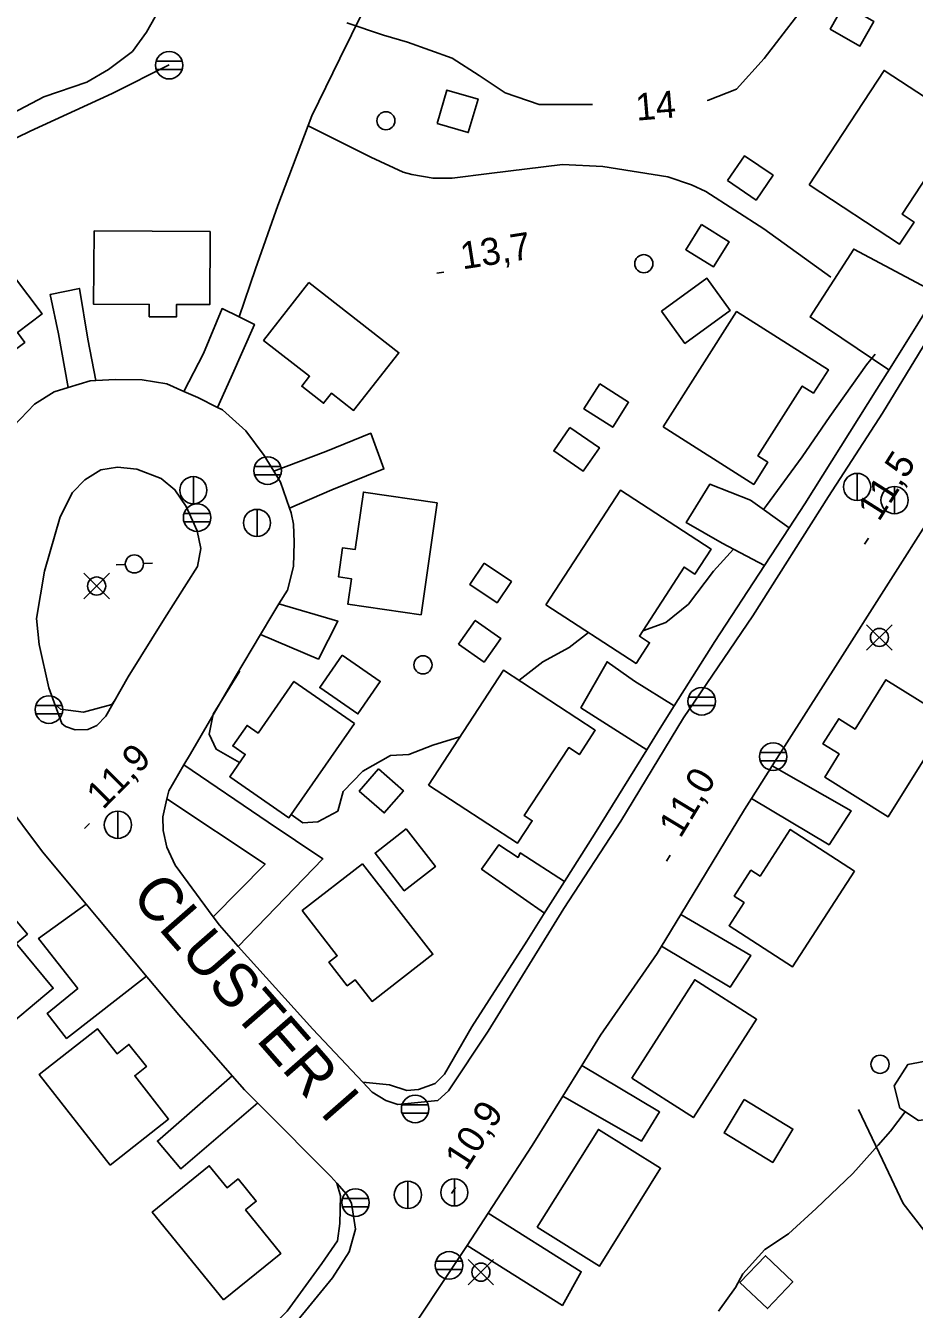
# Model space of a CAD drawing. Extents: x 646142 to 649934, y 5874075 to 5876351.
# Drawn here: x 647286.1 to 647384.4, y 5874712.1 to 5874854.1 of the extents above; entities that cross this region are included whole.
import ezdxf

# ---------------------------------------------------------------- set-up
doc = ezdxf.new("R2010")
doc.units = 0
for name, color, linetype in [('Niveau 1', 7, 'Continuous'), ('Niveau 15', 7, 'Continuous'), ('Niveau 19', 7, 'Continuous'), ('Niveau 2', 7, 'Continuous'), ('Niveau 21', 7, 'Continuous'), ('Niveau 22', 7, 'Continuous'), ('Niveau 3', 7, 'Continuous'), ('Niveau 31', 7, 'Continuous'), ('Niveau 36', 7, 'Continuous'), ('Niveau 4', 7, 'Continuous')]:
    doc.layers.add(name, color=color, linetype=linetype)

msp = doc.modelspace()

# ---------------------------------------------------------------- linework, layer by layer
at = {"layer": 'Niveau 1'}
msp.add_lwpolyline([(647362.71, 5874711.92), (647364.56, 5874714.57), (647365.4, 5874716.06), (647367.83, 5874718.75), (647370.42, 5874720.47), (647373.48, 5874723.29), (647377.56, 5874727.15), (647380.35, 5874730.3), (647381.72, 5874731.84), (647383.33, 5874734)], dxfattribs=at)
at = {"layer": 'Niveau 19'}
for points in [[(647386.86, 5874824.51), (647377.65, 5874829.4), (647372.83, 5874821.91), (647381.55, 5874816.04)], [(647290.78, 5874814.09), (647289.72, 5874820.05), (647288.81, 5874824.39), (647292.02, 5874825.05), (647292.94, 5874819.44), (647293.86, 5874814.87)], [(647303.58, 5874813.67), (647305.74, 5874817.85), (647307.81, 5874822.83), (647309.69, 5874821.91), (647311.38, 5874821.08), (647308.81, 5874815.24), (647307.29, 5874811.9)], [(647313.54, 5874804.83), (647319.29, 5874807.03), (647324.24, 5874809.04), (647325.69, 5874805.1), (647319.95, 5874802.78), (647315.26, 5874800.76)], [(647367.8, 5874794.42), (647363.1, 5874796.87), (647359.11, 5874799.17), (647361.73, 5874803.39), (647366.25, 5874801.62), (647370.51, 5874798.57)], [(647314.09, 5874790.16), (647320.61, 5874788.24), (647318.45, 5874784.06), (647312.06, 5874786.79)], [(647354.76, 5874774.03), (647347.49, 5874778.68), (647350.37, 5874783.76), (647353.4, 5874781.6), (647357.81, 5874778.89)], [(647303.59, 5874772.36), (647312.91, 5874766.03), (647318.95, 5874761.96), (647309.6, 5874752.27)], [(647368.64, 5874772.26), (647377.36, 5874767.28), (647374.93, 5874763.53), (647366.33, 5874768.63)], [(647306.81, 5874755.55), (647312.56, 5874761.38), (647301.7, 5874768.61)], [(647345.66, 5874759.45), (647340.78, 5874762.62), (647340.54, 5874762.13), (647338.42, 5874763.52), (647336.5, 5874760.84), (647343.46, 5874755.97)], [(647292.76, 5874756.96), (647287.52, 5874753.17), (647291.84, 5874747.64), (647288.47, 5874744.86), (647290.61, 5874742.11), (647299.43, 5874748.98)], [(647358.52, 5874755.81), (647366.26, 5874751.28), (647364, 5874747.78), (647356.4, 5874752.32)], [(647347.57, 5874739.09), (647356.19, 5874733.98), (647354.17, 5874730.74), (647345.49, 5874735.73)], [(647308.93, 5874737.97), (647300.65, 5874730.75), (647303.26, 5874727.66), (647311.74, 5874734.97)], [(647337.23, 5874722.77), (647347.52, 5874716.3), (647345.43, 5874712.58), (647334.9, 5874719.19)]]:
    msp.add_lwpolyline(points, dxfattribs=at)
at = {"layer": 'Niveau 2'}
for points in [[(647354.49, 5874871.09), (647359.08, 5874873.06), (647362.73, 5874876.86), (647365.08, 5874877.85), (647367.9, 5874878.83), (647371.65, 5874879.37), (647373.74, 5874878.88), (647375.58, 5874877.44), (647376.35, 5874875.13), (647376.55, 5874873.17), (647377.56, 5874868.38), (647377.64, 5874865.89), (647377.51, 5874863.72), (647376.44, 5874861), (647373.32, 5874857.73), (647367.74, 5874850.48), (647364.7, 5874847.1), (647361.6, 5874845.86), (647361.46, 5874845.85)], [(647301.22, 5874856.54), (647299.43, 5874853.4), (647297.89, 5874851.27), (647295.23, 5874849.26), (647292.86, 5874847.86), (647288.11, 5874846.23), (647283.22, 5874843.71), (647281.4, 5874842.6), (647274.57, 5874838.95), (647270.5, 5874836.4), (647267.73, 5874834.96), (647263.27, 5874833.3), (647258.98, 5874830.66), (647254.31, 5874826.48), (647252.48, 5874824.26), (647250.06, 5874819.3), (647248.47, 5874814.14), (647246.85, 5874811.65), (647246.13, 5874809.43)], [(647348.78, 5874845.41), (647342.87, 5874845.41), (647339.12, 5874846.67), (647336.24, 5874848.59), (647333.23, 5874850.51), (647328.32, 5874852.29), (647325.66, 5874853.08), (647321.61, 5874854.42)], [(647367.67, 5874800.6), (647367.99, 5874801.03), (647371.96, 5874806.44), (647375.02, 5874810.89), (647379.07, 5874816.59), (647380.02, 5874817.8)], [(647354.33, 5874787.19), (647356.88, 5874788.09), (647359.37, 5874790.14), (647362.16, 5874793.8), (647364.34, 5874796.22)], [(647340.63, 5874781.7), (647343.29, 5874783.77), (647346.18, 5874785.34), (647348.31, 5874787.01)], [(647309.68, 5874782.75), (647309.74, 5874782.69), (647306.82, 5874777.97), (647306.39, 5874775.77), (647307.15, 5874774.09), (647309.74, 5874772.61)], [(647289.28, 5874779.1), (647289.94, 5874778.52), (647292.49, 5874778.19), (647295.63, 5874779.03), (647295.87, 5874779.39)], [(647315.43, 5874766.86), (647316.75, 5874765.94), (647318.38, 5874766.04), (647320.6, 5874767.25), (647321.21, 5874769.41), (647323.38, 5874771.67), (647326.43, 5874773.38), (647328.47, 5874773.52), (647331.12, 5874774.54), (647334.1, 5874775.45)]]:
    msp.add_lwpolyline(points, dxfattribs=at)
at = {"layer": 'Niveau 21'}
for points in [[(647388.78, 5874824.3), (647380.85, 5874811.27), (647374.87, 5874802.04), (647366.48, 5874788.83), (647358.82, 5874777.56), (647351.88, 5874766.12), (647345.58, 5874756.49), (647337.21, 5874742.92), (647332.84, 5874736.29), (647331.65, 5874735.24), (647329.44, 5874735.02), (647327.23, 5874734.8), (647325.9, 5874735.25), (647324.4, 5874736.16), (647323.35, 5874737.27), (647317.82, 5874743.11), (647309.6, 5874752.27), (647307.51, 5874754.61), (647306.81, 5874755.55), (647302.61, 5874761.25), (647301.71, 5874763.27), (647301.29, 5874765.1), (647301.25, 5874766.61), (647301.7, 5874768.61), (647301.9, 5874769.48), (647303.59, 5874772.36), (647304.3, 5874773.57), (647309.3, 5874782.12), (647312.06, 5874786.79), (647313.41, 5874789.06), (647314.09, 5874790.16), (647315.02, 5874791.67), (647315.69, 5874794.31), (647315.77, 5874797), (647315.69, 5874798.97), (647315.44, 5874800.23), (647315.26, 5874800.76), (647314.28, 5874803.62), (647313.54, 5874804.83), (647312.46, 5874806.59), (647310.43, 5874809.3), (647307.85, 5874811.61), (647307.29, 5874811.9), (647305.13, 5874812.98), (647303.58, 5874813.67), (647301.7, 5874814.51), (647298.96, 5874814.93), (647296.03, 5874814.99), (647293.86, 5874814.87), (647293.23, 5874814.84)], [(647293.23, 5874814.84), (647290.78, 5874814.09), (647289.25, 5874813.63), (647287.05, 5874812.24), (647283.98, 5874809.02)], [(647301.45, 5874788.55), (647305.09, 5874794.28), (647305.47, 5874796.3), (647305.04, 5874798.24), (647303.84, 5874800.92), (647302.59, 5874802.78), (647301.06, 5874804.03), (647298.38, 5874805.05), (647296.25, 5874805.3), (647294.4, 5874805), (647292.64, 5874803.9), (647291.26, 5874802.48), (647289.89, 5874799.78), (647288.15, 5874793.77), (647287.27, 5874788.55), (647287.56, 5874785.66), (647288.63, 5874780.87), (647290.08, 5874776.92), (647290.47, 5874776.61), (647291.56, 5874776.25), (647292.96, 5874776.27), (647293.97, 5874776.72), (647294.93, 5874777.75), (647297.42, 5874782.08), (647301.45, 5874788.55)], [(647358.52, 5874755.81), (647365.56, 5874767.43), (647366.33, 5874768.63), (647368.64, 5874772.26), (647375.88, 5874783.64), (647386.6, 5874800.46)], [(647283.47, 5874768.71), (647287.94, 5874762.73), (647292.76, 5874756.96), (647294.07, 5874755.39), (647299.71, 5874748.65), (647303.01, 5874744.7), (647308.93, 5874737.97), (647310.3, 5874736.41), (647312.08, 5874734.62), (647319.84, 5874726.83), (647320.5, 5874726.09), (647321.56, 5874724.89), (647322.13, 5874723.89), (647322.54, 5874721.01), (647321.85, 5874718.48), (647320.03, 5874715.61), (647313.54, 5874707.71)], [(647327.95, 5874708.73), (647333.96, 5874717.75), (647334.9, 5874719.19), (647337.23, 5874722.77), (647342.09, 5874730.26), (647345.49, 5874735.73), (647347.57, 5874739.09), (647349.66, 5874742.47), (647355.91, 5874751.51), (647356.36, 5874752.25), (647358.52, 5874755.81)]]:
    msp.add_lwpolyline(points, dxfattribs=at)
at = {"layer": 'Niveau 22'}
for points in [[(647309.69, 5874821.91), (647311.5, 5874827.21), (647313.95, 5874834.21), (647317.74, 5874844.13), (647320.84, 5874850.49), (647325.98, 5874861.01), (647328.35, 5874865.31), (647330.56, 5874867.74), (647334.34, 5874871.3)], [(647317.33, 5874843.05), (647324.24, 5874839.59), (647327.82, 5874837.91), (647328.77, 5874837.67), (647331.14, 5874837.24), (647333.23, 5874837.26), (647337.35, 5874837.78), (647345.46, 5874838.75), (647349.9, 5874838.53), (647357.11, 5874837.38), (647359.72, 5874836.53), (647361.31, 5874835.77), (647367.71, 5874831.66), (647375.12, 5874826.3)], [(647323.35, 5874737.27), (647326.31, 5874736.97), (647328.25, 5874736.35), (647329.53, 5874736.47), (647331.35, 5874737.12), (647332.41, 5874738.16), (647335.41, 5874743.37), (647341.49, 5874752.86), (647343.35, 5874755.8), (647345.66, 5874759.45), (647348.98, 5874764.7), (647354.76, 5874774.03), (647356.24, 5874776.41), (647357.81, 5874778.89), (647362.3, 5874786), (647367.8, 5874794.42), (647370.51, 5874798.57), (647372.25, 5874801.23), (647380.22, 5874813.93), (647382.05, 5874816.84), (647387.44, 5874825.44)], [(647378.17, 5874734.25), (647380.85, 5874728.66), (647383.11, 5874723.85), (647385.41, 5874720.91)], [(647250.97, 5874680.43), (647253.53, 5874678.34), (647255.63, 5874677.25), (647256.83, 5874677.02), (647258.69, 5874677.2), (647261.06, 5874678.26), (647265.84, 5874680.96), (647272.1, 5874684.15), (647278.81, 5874687.78), (647280.57, 5874688.74), (647281.86, 5874689.4), (647289.51, 5874693.37), (647297.19, 5874697.64), (647301.94, 5874700.57), (647306.42, 5874703.94), (647309.99, 5874706.98), (647315.01, 5874711.93), (647318.82, 5874717.22), (647320.57, 5874719.73), (647320.84, 5874721.63), (647320.89, 5874724.68), (647320.5, 5874726.09)]]:
    msp.add_lwpolyline(points, dxfattribs=at)
at = {"layer": 'Niveau 3'}
for p, q in [((647331.55, 5874826.74), (647332.34, 5874826.87)), ((647378.86, 5874796.76), (647379.29, 5874797.44)), ((647292.59, 5874765.31), (647293.15, 5874765.88)), ((647356.96, 5874761.69), (647357.37, 5874762.38)), ((647333.17, 5874724.96), (647333.6, 5874725.63))]:
    msp.add_line(p, q, dxfattribs=at)
at = {"layer": 'Niveau 31'}
for points in [[(647376.6, 5874856.45), (647379.89, 5874854.57), (647378.34, 5874851.86), (647375.05, 5874853.74), (647376.6, 5874856.45)], [(647372.73, 5874836.5), (647381.01, 5874849.16), (647391.01, 5874842.62), (647389.3, 5874840.01), (647387.99, 5874840.86), (647383.02, 5874833.25), (647384.32, 5874832.4), (647382.73, 5874829.96), (647372.73, 5874836.5)], [(647331.58, 5874843.29), (647332.67, 5874847), (647336.11, 5874845.99), (647335.03, 5874842.29), (647331.58, 5874843.29)], [(647363.69, 5874836.99), (647365.58, 5874839.73), (647368.73, 5874837.57), (647366.85, 5874834.83), (647363.69, 5874836.99)], [(647293.64, 5874831.42), (647306.48, 5874831.35), (647306.44, 5874823.26), (647302.77, 5874823.28), (647302.76, 5874821.9), (647299.75, 5874821.92), (647299.75, 5874823.28), (647293.6, 5874823.31), (647293.64, 5874831.42)], [(647360.8, 5874832.11), (647363.86, 5874830.21), (647362.13, 5874827.44), (647359.07, 5874829.34), (647360.8, 5874832.11)], [(647272.93, 5874821.07), (647283.02, 5874828.69), (647287.89, 5874822.24), (647285.17, 5874820.18), (647285.99, 5874819.09), (647283.66, 5874817.33), (647282.8, 5874818.47), (647277.77, 5874814.67), (647272.93, 5874821.07)], [(647317.4, 5874825.72), (647327.35, 5874817.94), (647322.35, 5874811.56), (647319.91, 5874813.47), (647319.03, 5874812.35), (647316.61, 5874814.24), (647317.47, 5874815.34), (647312.39, 5874819.31), (647317.4, 5874825.72)], [(647356.4, 5874822.55), (647361.41, 5874826.18), (647364, 5874822.62), (647358.99, 5874818.98), (647356.4, 5874822.55)], [(647356.58, 5874809.73), (647364.69, 5874822.5), (647374.85, 5874816.06), (647373.2, 5874813.47), (647371.96, 5874814.26), (647367.05, 5874806.53), (647368.15, 5874805.83), (647366.59, 5874803.38), (647356.58, 5874809.73)], [(647349.56, 5874814.49), (647352.75, 5874812.47), (647351, 5874809.7), (647347.81, 5874811.72), (647349.56, 5874814.49)], [(647346.25, 5874809.68), (647349.52, 5874807.44), (647347.73, 5874804.84), (647344.47, 5874807.08), (647346.25, 5874809.68)], [(647343.62, 5874790.06), (647351.86, 5874802.74), (647361.88, 5874796.23), (647360.08, 5874793.46), (647358.9, 5874794.23), (647353.95, 5874786.6), (647355.08, 5874785.87), (647353.59, 5874783.58), (647343.62, 5874790.06)], [(647331.59, 5874801.34), (647329.81, 5874788.96), (647321.71, 5874790.13), (647322.11, 5874792.95), (647320.67, 5874793.16), (647321.13, 5874796.37), (647322.51, 5874796.17), (647323.43, 5874802.52), (647331.59, 5874801.34)], [(647336.78, 5874794.66), (647339.8, 5874792.63), (647338.21, 5874790.28), (647335.19, 5874792.31), (647336.78, 5874794.66)], [(647333.95, 5874785.71), (647335.79, 5874788.34), (647338.62, 5874786.35), (647336.78, 5874783.72), (647333.95, 5874785.71)], [(647321.08, 5874784.5), (647325.29, 5874781.59), (647322.82, 5874778), (647318.61, 5874780.91), (647321.08, 5874784.5)], [(647330.62, 5874770.12), (647338.92, 5874782.82), (647349.07, 5874776.18), (647347.32, 5874773.5), (647346.14, 5874774.27), (647341.22, 5874766.75), (647342.1, 5874766.17), (647340.47, 5874763.68), (647330.62, 5874770.12)], [(647322.43, 5874776.94), (647315.19, 5874766.51), (647308.65, 5874771.05), (647310.36, 5874773.51), (647308.99, 5874774.46), (647310.57, 5874776.73), (647311.79, 5874775.88), (647315.75, 5874781.58), (647322.43, 5874776.94)], [(647388.2, 5874777.42), (647381.47, 5874766.62), (647374.45, 5874771), (647376.04, 5874773.56), (647374.25, 5874774.67), (647375.99, 5874777.46), (647377.8, 5874776.32), (647381.21, 5874781.78), (647388.2, 5874777.42)], [(647325.1, 5874771.91), (647327.86, 5874769.5), (647325.73, 5874767.05), (647322.97, 5874769.46), (647325.1, 5874771.91)], [(647328.17, 5874765.27), (647331.4, 5874761.1), (647327.95, 5874758.43), (647324.72, 5874762.6), (647328.17, 5874765.27)], [(647377.75, 5874760.6), (647370.87, 5874750.01), (647363.86, 5874754.56), (647365.53, 5874757.13), (647364.43, 5874757.84), (647366.29, 5874760.71), (647367.29, 5874760.06), (647370.64, 5874765.22), (647377.75, 5874760.6)], [(647323.32, 5874761.42), (647331.11, 5874751.42), (647324.39, 5874746.19), (647322.51, 5874748.59), (647321.65, 5874747.92), (647319.62, 5874750.53), (647320.54, 5874751.25), (647316.66, 5874756.24), (647323.32, 5874761.42)], [(647282.86, 5874742.41), (647274.68, 5874752.21), (647281.06, 5874757.53), (647283.03, 5874755.16), (647284.2, 5874756.14), (647286.28, 5874753.65), (647285.02, 5874752.6), (647289.14, 5874747.66), (647282.86, 5874742.41)], [(647353.1, 5874737.71), (647360.07, 5874748.6), (647366.9, 5874744.22), (647359.93, 5874733.34), (647353.1, 5874737.71)], [(647295.41, 5874728.09), (647287.56, 5874738.1), (647294.02, 5874743.17), (647296.19, 5874740.41), (647297.5, 5874741.44), (647299.43, 5874738.98), (647298.14, 5874737.97), (647301.89, 5874733.18), (647295.41, 5874728.09)], [(647390.54, 5874735.69), (647388.98, 5874735.42), (647387.6, 5874733.41), (647384.81, 5874733.02), (647382.74, 5874734.4), (647382.13, 5874736.85), (647383.65, 5874739.23), (647386.19, 5874739.71), (647388.02, 5874738.43), (647389.81, 5874738.72), (647390.54, 5874735.69)], [(647365.55, 5874735.33), (647370.92, 5874732.07), (647368.69, 5874728.39), (647363.31, 5874731.65), (647365.55, 5874735.33)], [(647342.66, 5874721.22), (647349.41, 5874732.04), (647356.3, 5874727.74), (647349.55, 5874716.92), (647342.66, 5874721.22)], [(647307.97, 5874713.19), (647300.09, 5874722.9), (647306.38, 5874728.01), (647308.35, 5874725.58), (647309.57, 5874726.57), (647311.58, 5874724.09), (647310.4, 5874723.13), (647314.3, 5874718.32), (647307.97, 5874713.19)], [(647365.07, 5874715.09), (647367.88, 5874718.06), (647370.91, 5874715.18), (647368.1, 5874712.22), (647365.07, 5874715.09)]]:
    msp.add_lwpolyline(points, dxfattribs=at)
at = {"layer": 'Niveau 36'}
for p, q in [((647303.38, 5874850.19), (647300.5, 5874850.19)), ((647300.5, 5874849.27), (647303.38, 5874849.27)), ((647304.63, 5874801.23), (647304.63, 5874804.23)), ((647314.28, 5874805.35), (647311.4, 5874805.35)), ((647311.4, 5874804.43), (647314.28, 5874804.43)), ((647378.04, 5874801.59), (647378.04, 5874804.59)), ((647382.17, 5874800.13), (647382.17, 5874803.13)), ((647306.48, 5874800.15), (647303.6, 5874800.15)), ((647311.67, 5874797.61), (647311.67, 5874800.61)), ((647303.6, 5874799.23), (647306.48, 5874799.23)), ((647296.1, 5874794.49), (647297.1, 5874794.53)), ((647300.1, 5874794.68), (647299.1, 5874794.63)), ((647295.34, 5874790.73), (647292.52, 5874793.55)), ((647292.52, 5874790.73), (647295.34, 5874793.55)), ((647381.9, 5874785.04), (647379.08, 5874787.86)), ((647379.08, 5874785.04), (647381.9, 5874787.86)), ((647290.1, 5874778.92), (647287.22, 5874778.92)), ((647362.28, 5874779.84), (647359.4, 5874779.84)), ((647359.4, 5874778.92), (647362.28, 5874778.92)), ((647287.22, 5874778), (647290.1, 5874778)), ((647370.18, 5874773.72), (647367.3, 5874773.72)), ((647367.3, 5874772.8), (647370.18, 5874772.8)), ((647296.29, 5874764.22), (647296.29, 5874767.22)), ((647330.59, 5874734.75), (647327.71, 5874734.75)), ((647327.71, 5874733.83), (647330.59, 5874733.83)), ((647328.36, 5874723.29), (647328.36, 5874726.29)), ((647333.5, 5874723.56), (647333.5, 5874726.56)), ((647324, 5874724.39), (647321.12, 5874724.39)), ((647321.12, 5874723.47), (647324, 5874723.47)), ((647337.83, 5874714.84), (647335.01, 5874717.66)), ((647335.01, 5874714.84), (647337.83, 5874717.66)), ((647334.34, 5874717.45), (647331.46, 5874717.45)), ((647331.46, 5874716.53), (647334.34, 5874716.53))]:
    msp.add_line(p, q, dxfattribs=at)
for centre, radius in [((647301.95, 5874849.74), 1.52), ((647325.92, 5874843.6), 1), ((647354.44, 5874827.79), 1), ((647312.84, 5874804.9), 1.52), ((647304.62, 5874802.74), 1.5), ((647378.03, 5874803.1), 1.5), ((647382.16, 5874801.64), 1.5), ((647305.04, 5874799.7), 1.52), ((647311.66, 5874799.12), 1.5), ((647298.1, 5874794.58), 1), ((647293.93, 5874792.14), 1), ((647380.49, 5874786.45), 1), ((647330.02, 5874783.42), 1), ((647288.66, 5874778.47), 1.52), ((647360.84, 5874779.39), 1.52), ((647368.74, 5874773.27), 1.52), ((647296.28, 5874765.73), 1.5), ((647380.56, 5874739.24), 1), ((647329.15, 5874734.3), 1.52), ((647328.35, 5874724.8), 1.5), ((647333.49, 5874725.07), 1.5), ((647322.56, 5874723.94), 1.52), ((647332.9, 5874717), 1.52), ((647336.42, 5874716.25), 1)]:
    msp.add_circle(centre, radius, dxfattribs=at)
at = {"layer": 'Niveau 4'}
msp.add_lwpolyline([(647249.17, 5874793.87), (647249.03, 5874796.78), (647249.46, 5874804.17), (647251.06, 5874809.23), (647252.45, 5874815.19), (647252.63, 5874818.12), (647253.37, 5874820.06), (647257.63, 5874825.49), (647261.57, 5874828.21), (647265.94, 5874831.32), (647268.49, 5874833.9), (647275.55, 5874838.03), (647280.78, 5874839.66), (647286.59, 5874842.45), (647295.65, 5874846.6), (647301.96, 5874849.77)], dxfattribs=at)

# ---------------------------------------------------------------- texts
at = {"layer": 'Niveau 15'}
msp.add_text('CLUSTER I', height=4.8, rotation=311.1859, dxfattribs=at).set_placement((647297.62, 5874757.74))
at = {"layer": 'Niveau 2'}
msp.add_text('14', height=3, rotation=4.8778, dxfattribs=at).set_placement((647353.64, 5874843.6))
at = {"layer": 'Niveau 3'}
for s, rotation, p in [('13,7 ', 8.941, (647334.4, 5874827.15)), ('11,5 ', 57.6835, (647380.44, 5874799.17)), ('11,9 ', 45.2459, (647294.64, 5874767.33)), ('11,0 ', 58.7936, (647358.48, 5874764.14)), ('10,9 ', 57.018, (647334.77, 5874727.35))]:
    msp.add_text(s, height=3, rotation=rotation, dxfattribs=at).set_placement(p)

doc.saveas('drawing.dxf')
